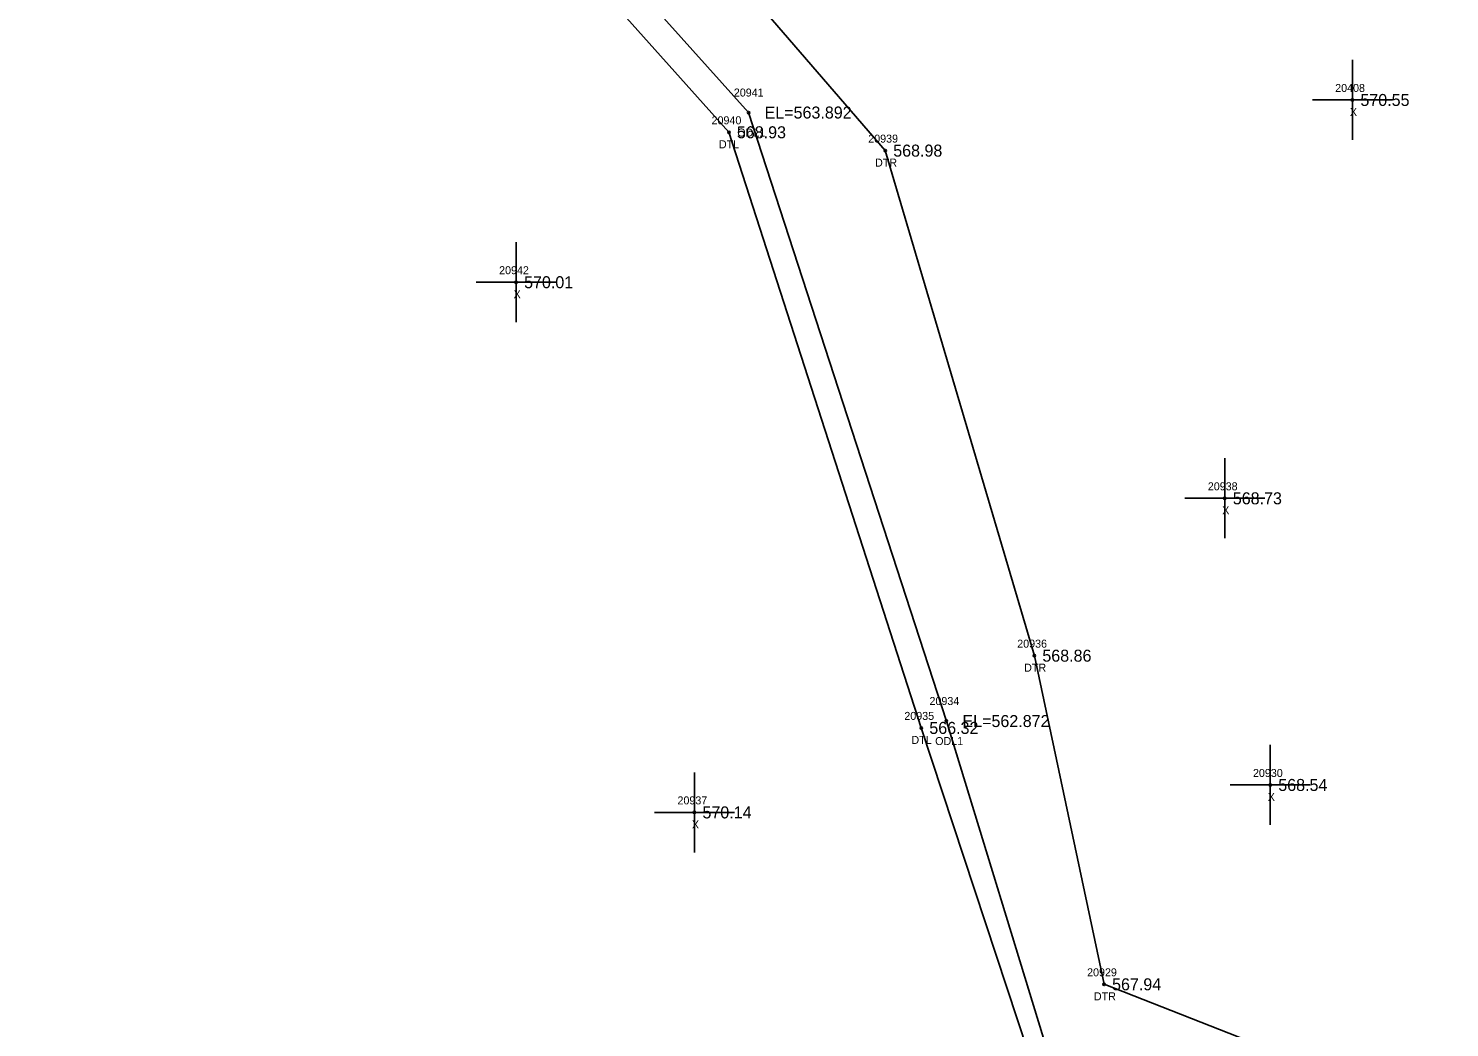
# Model space of a CAD drawing. Extents: x 1695443 to 1696344, y 1087542 to 1090645.
# Drawn here: x 1695474.5 to 1695652.1, y 1089115.6 to 1089240.5 of the extents above; entities that cross this region are included whole.
import ezdxf

# ---------------------------------------------------------------- set-up
doc = ezdxf.new("R2010")
doc.units = 0
for name, color, linetype in [('RD_EX_H2O', 7, 'Continuous'), ('RD_EX_H2O_txCode', 7, 'Continuous'), ('RD_EX_Misc', 7, 'Continuous'), ('RD_EX_Misc_txCode', 7, 'Continuous'), ('RD_EX_TX_H2O_ELEV', 7, 'Continuous'), ('RD_EX_TX_Misc_ELEV', 7, 'Continuous'), ('RD_SMD_Locator', 7, 'Continuous')]:
    doc.layers.add(name, color=color, linetype=linetype)

msp = doc.modelspace()

# ---------------------------------------------------------------- linework, layer by layer
at = {"layer": 'RD_EX_H2O'}
for points in [[(1695741.44, 1088979.77), (1695735.36, 1088982.13), (1695733.74, 1089010.53), (1695714.12, 1089041.46), (1695688.87, 1089060.37), (1695655.87, 1089102.57), (1695608.91, 1089121.01), (1695600.2, 1089162.09), (1695581.57, 1089225.22), (1695514.41, 1089303.03), (1695500.66, 1089306.61), (1695490.41, 1089302.07), (1695489.34, 1089311.94), (1695498.55, 1089320.55), (1695495.21, 1089339.52)], [(1695727.71, 1088968.15), (1695711.81, 1088974.31), (1695709.85, 1089000.95), (1695713.57, 1089012.1), (1695692.24, 1089031.37), (1695674.55, 1089053.33), (1695643.83, 1089091.02), (1695600.78, 1089108.48), (1695586.08, 1089153.06), (1695562.04, 1089227.51), (1695501.97, 1089294.68), (1695480.62, 1089297.16), (1695479.18, 1089314.76), (1695479.78, 1089327.68), (1695474.54, 1089335.41)], [(1695742.91, 1088967.28), (1695718.08, 1088980.23), (1695718.13, 1089011.92), (1695699.88, 1089034.17), (1695684.21, 1089056.74), (1695648.51, 1089095.47), (1695602.44, 1089110.75), (1695589.22, 1089153.92), (1695564.5, 1089229.98), (1695504.85, 1089296.49), (1695485.1, 1089301.93), (1695482.27, 1089302.79), (1695487.67, 1089314.21), (1695485.89, 1089334.31)]]:
    msp.add_lwpolyline(points, dxfattribs=at)
at = {"layer": 'RD_EX_Misc'}
for p, q in [((1695639.93, 1089226.55), (1695639.93, 1089236.55)), ((1695634.93, 1089231.55), (1695644.93, 1089231.55)), ((1695535.46, 1089203.77), (1695535.46, 1089213.77)), ((1695530.46, 1089208.77), (1695540.46, 1089208.77)), ((1695623.99, 1089176.76), (1695623.99, 1089186.76)), ((1695618.99, 1089181.76), (1695628.99, 1089181.76)), ((1695629.67, 1089140.93), (1695629.67, 1089150.93)), ((1695557.74, 1089137.5), (1695557.74, 1089147.5)), ((1695624.67, 1089145.93), (1695634.67, 1089145.93)), ((1695552.74, 1089142.5), (1695562.74, 1089142.5))]:
    msp.add_line(p, q, dxfattribs=at)
at = {"layer": 'RD_SMD_Locator'}
for centre in [(1695639.93, 1089231.55), (1695564.5, 1089229.98), (1695562.04, 1089227.51), (1695581.57, 1089225.22), (1695535.46, 1089208.77), (1695623.99, 1089181.76), (1695600.2, 1089162.09), (1695586.08, 1089153.06), (1695589.22, 1089153.92), (1695629.67, 1089145.93), (1695557.74, 1089142.5), (1695608.91, 1089121.01)]:
    msp.add_circle(centre, 0.15, dxfattribs=at)

# ---------------------------------------------------------------- texts
at = {"layer": 'RD_EX_H2O_txCode'}
for s, p in [('20941', (1695562.66, 1089231.98)), ('20940', (1695559.88, 1089228.51)), ('ODL1', (1695563.09, 1089226.98)), ('DTL', (1695560.8, 1089225.51)), ('20939', (1695579.45, 1089226.22)), ('DTR', (1695580.3, 1089223.22)), ('20936', (1695598.06, 1089163.09)), ('DTR', (1695598.93, 1089160.09)), ('20934', (1695587.1, 1089155.92)), ('20935', (1695583.96, 1089154.06)), ('DTL', (1695584.84, 1089151.06)), ('ODL1', (1695587.81, 1089150.92)), ('20929', (1695606.79, 1089122.01)), ('DTR', (1695607.64, 1089119.01))]:
    msp.add_text(s, height=1, dxfattribs=at).set_placement(p)
at = {"layer": 'RD_EX_Misc_txCode'}
for s, p in [('20408', (1695637.78, 1089232.55)), ('X', (1695639.62, 1089229.55)), ('20942', (1695533.34, 1089209.77)), ('X', (1695535.15, 1089206.77)), ('20938', (1695621.87, 1089182.76)), ('X', (1695623.67, 1089179.76)), ('20930', (1695627.51, 1089146.93)), ('20937', (1695555.62, 1089143.5)), ('X', (1695629.36, 1089143.93)), ('X', (1695557.42, 1089140.5))]:
    msp.add_text(s, height=1, dxfattribs=at).set_placement(p)
at = {"layer": 'RD_EX_TX_H2O_ELEV'}
for s, p in [('EL=563.892', (1695566.5, 1089229.23)), ('568.93', (1695563.04, 1089226.76)), ('568.98', (1695582.57, 1089224.47)), ('568.86', (1695601.2, 1089161.34)), ('EL=562.872', (1695591.22, 1089153.17)), ('566.32', (1695587.08, 1089152.31)), ('567.94', (1695609.91, 1089120.26))]:
    msp.add_text(s, height=1.5, dxfattribs=at).set_placement(p)
at = {"layer": 'RD_EX_TX_Misc_ELEV'}
for s, p in [('570.55', (1695640.93, 1089230.8)), ('570.01', (1695536.46, 1089208.02)), ('568.73', (1695624.99, 1089181.01)), ('568.54', (1695630.67, 1089145.18)), ('570.14', (1695558.74, 1089141.75))]:
    msp.add_text(s, height=1.5, dxfattribs=at).set_placement(p)

doc.saveas('drawing.dxf')
